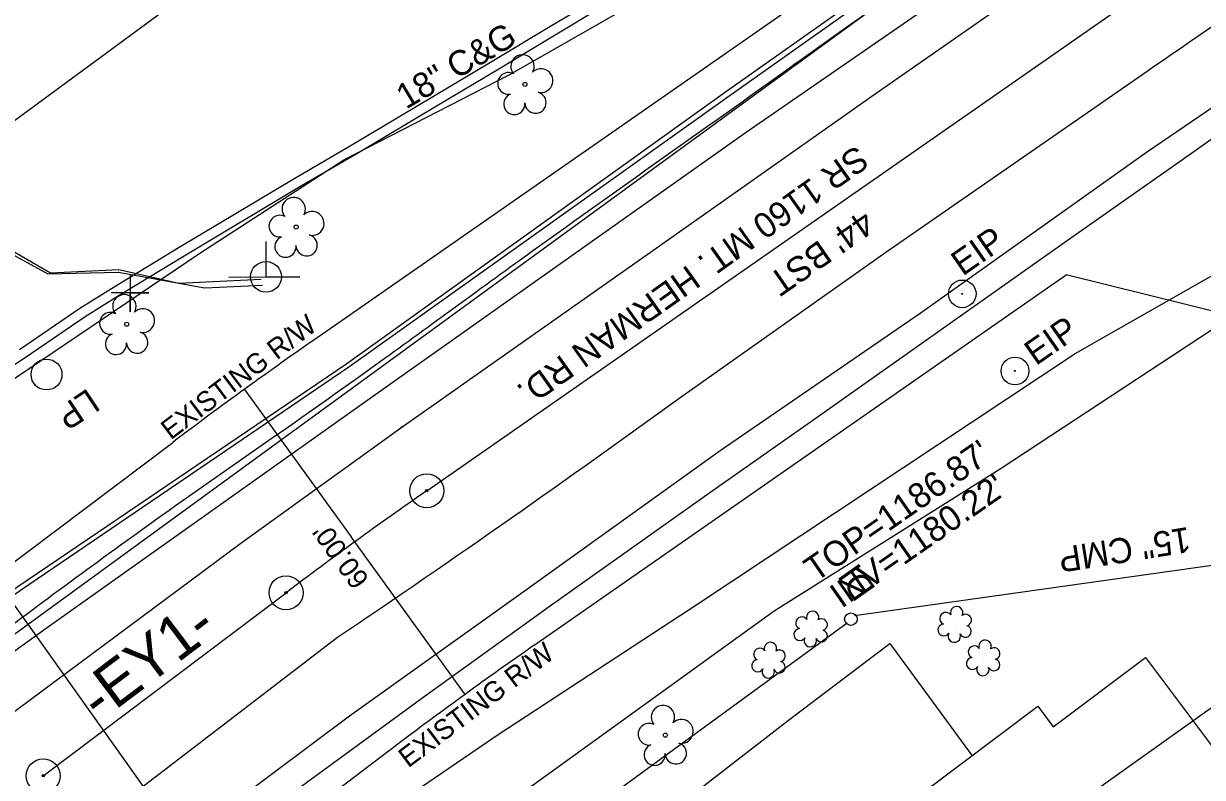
# Model space of a CAD drawing. Extents: x 1262092 to 1264624, y 774970 to 778314.
# Drawn here: x 1263058.9 to 1263246.8, y 776337.8 to 776457.9 of the extents above; entities that cross this region are included whole.
import ezdxf

# ---------------------------------------------------------------- set-up
doc = ezdxf.new("R2010")
doc.units = 0
for name, color, linetype in [('COGO Default Parcel', 7, 'Continuous'), ('Exist DTM Spot Elevation CELL', 7, 'Continuous'), ('Exist Horizontal Alignment', 7, 'Continuous'), ('Exist Horizontal Alignment Direction Label', 7, 'Continuous'), ('Exist Horizontal Alignment Tick Label', 7, 'Continuous'), ('Exist Horizontal Alignment Tick Large', 7, 'Continuous'), ('Exist Horizontal Alignment Tick Small', 7, 'Continuous'), ('Exist Property Iron Pin CELL', 7, 'Continuous'), ('Exist Property Iron Pin Text', 7, 'Continuous'), ('Exist Right of Way Line', 7, 'Continuous'), ('Exist Right of Way Line Text', 7, 'Continuous'), ('Exist Right of Way Width CELL', 7, 'Continuous'), ('Exist Roads Curbs', 7, 'Continuous'), ('Exist Roads EOP', 7, 'Continuous'), ('Exist Roads EOP Other', 7, 'Continuous'), ('Exist Roads EOT', 7, 'Continuous'), ('Exist Structure Minor Drop Inlet', 7, 'Continuous'), ('Exist Structure Minor Drop Inlet Text', 7, 'Continuous'), ('Exist Structure Minor Drop Inlet Top Elevation', 7, 'Continuous'), ('Exist Structure Minor Pipes CMP 15 Inch', 7, 'Continuous'), ('Exist Structure Minor Pipes CMP 15 Inch Invert', 7, 'Continuous'), ('Exist Structure Minor Pipes CMP 15 Inch Text', 7, 'Continuous'), ('Exist Utilities Gas UG Line SUE LOS B', 7, 'Continuous'), ('Exist Utilities Other Pole Text', 7, 'Continuous'), ('Exist Utilities Power Joint Use Telephone CELL', 7, 'Continuous'), ('Exist Utilities Power UG Cable SUE LOS B', 7, 'Continuous'), ('Exist Utilities Sanitary Sewer UG Line', 7, 'Continuous'), ('Exist Utilities Telephone UG Conduit SUE LOS B', 7, 'Continuous'), ('Exist Utilities Telephone UG FO SUE LOS B', 7, 'Continuous'), ('Exist Utilities TV UG FO Cable SUE LOS B', 7, 'Continuous'), ('Prop Horizontal Alignment', 7, 'Continuous'), ('Prop Shade Medium', 7, 'Continuous'), ('Prop Superelevation Label', 7, 'Continuous'), ('Sheet Sticker Incomplete CELL', 7, 'Continuous'), ('Typical Text Label CELL', 7, 'Continuous')]:
    doc.layers.add(name, color=color, linetype=linetype)

# ---------------------------------------------------------------- blocks, each defined once
blk = doc.blocks.new('EXIST DTM SPOT ELEVATION')
at = {"layer": 'Exist DTM Spot Elevation CELL'}
blk.add_lwpolyline([(0, 0.06), (0, -0.06), (0, 0), (0.06, 0), (-0.06, 0)], dxfattribs=at)
blk = doc.blocks.new('EXIST PROPERTY IRON PIN')
at = {"layer": 'Exist Property Iron Pin CELL'}
for radius in [0.0441, 0.00141]:
    blk.add_circle((0, 0), radius, dxfattribs=at)

msp = doc.modelspace()

# ---------------------------------------------------------------- linework, layer by layer
at = {"layer": 'COGO Default Parcel'}
for p, q in [((1263129.41, 776264.25), (1263013.38, 776427.15)), ((1263276.19, 776368.79), (1263129.41, 776264.25))]:
    msp.add_line(p, q, dxfattribs=at)
at = {"layer": 'Exist Horizontal Alignment'}
for p, q in [((1263123.18, 776383.49), (1263698.47, 776784.16)), ((1263062.04, 776338.06), (1263100.74, 776367.24))]:
    msp.add_line(p, q, dxfattribs=at)
msp.add_arc((1263531.93, 775795.39), 716.2, 124.8, 127.01667, dxfattribs=at)
at = {"layer": 'Exist Horizontal Alignment Tick Label'}
for centre, radius in [((1263123.18, 776383.49), 2.71), ((1263123.18, 776383.49), 0.187), ((1263100.74, 776367.24), 2.71), ((1263100.74, 776367.24), 0.187), ((1263062.04, 776338.06), 2.71), ((1263062.04, 776338.06), 0.187)]:
    msp.add_circle(centre, radius, dxfattribs=at)
at = {"layer": 'Exist Horizontal Alignment Tick Large'}
for p, q in [((1263184.45, 776361.28), (1263184.45, 776361.28)), ((1263207.4, 776362.01), (1263207.4, 776362.01)), ((1263177.73, 776356.31), (1263177.73, 776356.31)), ((1263211.94, 776356.67), (1263211.94, 776356.67))]:
    msp.add_line(p, q, dxfattribs=at)
for centre, radius, start, end in [((1263207.63, 776364.05), 0.99, 334.8391, 200.4717), ((1263182.97, 776362.41), 0.968, 35.8908, 245.4216), ((1263184.68, 776363.32), 0.99, 334.8391, 200.4717), ((1263205.92, 776363.13), 0.968, 35.8908, 245.4216), ((1263209.07, 776362.88), 0.929, 284.4567, 126.0861), ((1263182.65, 776360.57), 0.955, 95.1099, 327.9534), ((1263186.09, 776360.35), 0.937, 204.9913, 73.4601), ((1263186.12, 776362.15), 0.929, 284.4567, 126.0861), ((1263205.6, 776361.3), 0.955, 95.1099, 327.9534), ((1263209.04, 776361.08), 0.937, 204.9913, 73.4601), ((1263177.96, 776358.35), 0.99, 334.8391, 200.4717), ((1263184.32, 776359.6), 0.984, 151.2797, 21.387), ((1263207.27, 776360.32), 0.984, 151.2797, 21.387), ((1263212.17, 776358.71), 0.99, 334.8391, 200.4717), ((1263176.25, 776357.44), 0.968, 35.8908, 245.4216), ((1263179.4, 776357.18), 0.929, 284.4567, 126.0861), ((1263210.46, 776357.8), 0.968, 35.8908, 245.4216), ((1263213.61, 776357.54), 0.929, 284.4567, 126.0861), ((1263175.93, 776355.61), 0.955, 95.1099, 327.9534), ((1263179.37, 776355.38), 0.937, 204.9913, 73.4601), ((1263210.14, 776355.96), 0.955, 95.1099, 327.9534), ((1263213.58, 776355.74), 0.937, 204.9913, 73.4601), ((1263177.6, 776354.63), 0.984, 151.2797, 21.387), ((1263211.81, 776354.99), 0.984, 151.2797, 21.387)]:
    msp.add_arc(centre, radius, start, end, dxfattribs=at)
at = {"layer": 'Exist Horizontal Alignment Tick Small'}
for p, q in [((1263138.82, 776448.25), (1263138.82, 776448.25)), ((1263102.35, 776425.51), (1263102.35, 776425.51)), ((1263075.35, 776410.02), (1263075.35, 776410.02)), ((1263161.21, 776344.54), (1263161.21, 776344.54))]:
    msp.add_line(p, q, dxfattribs=at)
for centre in [(1263138.82, 776448.25), (1263102.35, 776425.51), (1263075.35, 776410.02), (1263161.21, 776344.54)]:
    msp.add_circle(centre, 0.326, dxfattribs=at)
for centre, radius, start, end in [((1263138.44, 776451.13), 1.86, 330.1651, 219.7134), ((1263136.22, 776448.41), 1.73, 62.6636, 279.3457), ((1263141.37, 776448.84), 1.9, 257.1011, 134.1999), ((1263137.12, 776445.13), 1.69, 111.5671, 6.231), ((1263140.5, 776445.35), 1.7, 181.2822, 74.56), ((1263101.97, 776428.38), 1.86, 330.1651, 219.7134), ((1263099.75, 776425.66), 1.73, 62.6636, 279.3457), ((1263104.9, 776426.09), 1.9, 257.1011, 134.1999), ((1263100.65, 776422.39), 1.69, 111.5671, 6.231), ((1263104.03, 776422.61), 1.7, 181.2822, 74.56), ((1263074.97, 776412.89), 1.86, 330.1651, 219.7134), ((1263077.9, 776410.6), 1.9, 257.1011, 134.1999), ((1263072.75, 776410.17), 1.73, 62.6636, 279.3457), ((1263073.65, 776406.89), 1.69, 111.5671, 6.231), ((1263077.02, 776407.12), 1.7, 181.2822, 74.56), ((1263160.82, 776347.41), 1.86, 330.1651, 219.7134), ((1263158.6, 776344.69), 1.73, 62.6636, 279.3457), ((1263163.76, 776345.13), 1.9, 257.1011, 134.1999), ((1263159.5, 776341.42), 1.69, 111.5671, 6.231), ((1263162.88, 776341.64), 1.7, 181.2822, 74.56)]:
    msp.add_arc(centre, radius, start, end, dxfattribs=at)
at = {"layer": 'Exist Right of Way Line'}
for p, q in [((1263106.05, 776408.12), (1263226.42, 776491.95)), ((1263350.65, 776386.89), (1263225.07, 776417.89)), ((1263043.98, 776362.02), (1263082.68, 776391.2)), ((1263080.1, 776314.11), (1263118.8, 776343.29))]:
    msp.add_line(p, q, dxfattribs=at)
msp.add_lwpolyline([(1263140.3, 776358.86), (1263140.32, 776358.87), (1263225.07, 776417.89)], dxfattribs=at)
for centre, radius, start, end in [((1263531.93, 775795.39), 746.2, 124.80113, 127.01667), ((1263585.26, 775720.24), 778.35, 124.86679, 125.86153), ((1263531.93, 775795.39), 686.2, 125.92832, 127.01667)]:
    msp.add_arc(centre, radius, start, end, dxfattribs=at)
at = {"layer": 'Exist Right of Way Width CELL'}
for p in [(1263094.11, 776399.65), (1263129.28, 776351.04)]:
    msp.add_line(p, (1263111.13, 776376.13), dxfattribs=at)
at = {"layer": 'Exist Roads Curbs'}
msp.add_lwpolyline([(1263216.03, 776506.6), (1263213.8, 776504.87), (1263209.23, 776501.42), (1263199.46, 776494.02), (1263185.09, 776483.09), (1263175.96, 776476.24), (1263172.02, 776473.25), (1263167.68, 776470.14), (1263159.5, 776465.39), (1263151.22, 776460.64), (1263143.62, 776456.08), (1263134.41, 776450.52), (1263125.08, 776444.97), (1263112.03, 776437.18), (1263102.92, 776431.9), (1263084.51, 776420.89), (1263074.17, 776414.6), (1263068.75, 776411.21), (1263059.14, 776404.65), (1263050.93, 776399.25)], dxfattribs=at)
at = {"layer": 'Exist Roads EOP'}
msp.add_lwpolyline([(1263305.84, 776482.42), (1263293.83, 776475.54), (1263265.44, 776456.13), (1263237.91, 776437.41), (1263201.8, 776411.74), (1263169.95, 776389.85), (1263138.16, 776367.04), (1263110.85, 776347.57), (1263079.86, 776324.43)], dxfattribs=at)
msp.add_spline([(1263270.33, 776616.29), (1263277.95, 776601.77), (1263283.55, 776577.66), (1263282.77, 776555.16), (1263273.97, 776526.11), (1263261.3, 776509.47), (1263242.63, 776493.72), (1263207.21, 776469.34), (1263177.26, 776448.17), (1263136.42, 776419.06), (1263111.74, 776401.16), (1263077.88, 776377.33), (1263049.63, 776356.49)], degree=3, dxfattribs=at)
at = {"layer": 'Exist Roads EOP Other'}
msp.add_lwpolyline([(1263175.16, 776477.62), (1263175, 776477.5), (1263171.08, 776474.52), (1263166.82, 776471.47), (1263158.71, 776466.76), (1263150.42, 776462), (1263142.8, 776457.43), (1263133.6, 776451.88), (1263124.27, 776446.33), (1263111.23, 776438.54), (1263102.12, 776433.26), (1263083.7, 776422.25), (1263073.34, 776415.94), (1263067.89, 776412.54), (1263058.26, 776405.96)], dxfattribs=at)
at = {"layer": 'Exist Roads EOT'}
msp.add_line((1263068.23, 776328.99), (1263108.97, 776360.14), dxfattribs=at)
for points in [[(1263055.86, 776347.14), (1263093.56, 776375.13), (1263119.4, 776393.79), (1263119.03, 776393.52), (1263161.16, 776423.14), (1263194.13, 776446.35), (1263238.24, 776477.15), (1263266.32, 776496.83), (1263297.06, 776517.2), (1263326.49, 776538.85)], [(1263163.71, 776398.45), (1263196.36, 776421.53), (1263237.98, 776450.36)]]:
    msp.add_lwpolyline(points, dxfattribs=at)
msp.add_ellipse((1261990.55, 778026.7), major_axis=(1423.31, 1437.35), ratio=0.9919, start_param=4.514715, end_param=4.547755, dxfattribs=at)
msp.add_spline([(1263237.98, 776450.36), (1263259.66, 776465.25), (1263288.73, 776485.12), (1263318.56, 776505.53), (1263341.21, 776520.98)], degree=3, dxfattribs=at)
at = {"layer": 'Exist Structure Minor Drop Inlet'}
msp.add_circle((1263190.78, 776363.02), 1, dxfattribs=at)
at = {"layer": 'Exist Structure Minor Pipes CMP 15 Inch'}
for p, q in [((1263252.08, 776372.11), (1263191.34, 776363.55)), ((1263190.16, 776362.41), (1263109.03, 776303.24))]:
    msp.add_line(p, q, dxfattribs=at)
at = {"layer": 'Exist Utilities Gas UG Line SUE LOS B'}
msp.add_lwpolyline([(1263088.04, 776312.91), (1263134.74, 776344.77), (1263166.36, 776365.45), (1263226.51, 776405.34), (1263250.34, 776418.92), (1263298.57, 776447.74), (1263334.08, 776473.24), (1263349.9, 776479.97), (1263361.13, 776478.82), (1263375.51, 776470.89), (1263383.73, 776466.14), (1263405.71, 776440.43), (1263407.22, 776439.34), (1263410.02, 776440.45), (1263416.58, 776444.66), (1263442.39, 776461.54), (1263455.06, 776469.2), (1263497.14, 776495.83), (1263506.92, 776503.01), (1263523.32, 776512.13)], dxfattribs=at)
msp.add_circle((1263062.57, 776402.01), 2.46, dxfattribs=at)
at = {"layer": 'Exist Utilities Power Joint Use Telephone CELL'}
msp.add_line((1263097.55, 776417.57), (1263097.55, 776417.57), dxfattribs=at)
msp.add_lwpolyline([(1263091.61, 776417.57), (1263102.95, 776417.54), (1263097.55, 776417.55), (1263097.55, 776423.2)], dxfattribs=at)
msp.add_circle((1263097.55, 776417.58), 2.45, dxfattribs=at)
at = {"layer": 'Exist Utilities Power UG Cable SUE LOS B'}
for points in [[(1263022.78, 776438.19), (1263051.86, 776397.67), (1263087, 776421.34), (1263109.96, 776436.23), (1263136.29, 776449.79), (1263136.3, 776449.76), (1263171.16, 776469.68), (1263198.08, 776488.52), (1263216, 776499.92), (1263233.17, 776512.29), (1263248.6, 776528.82), (1263250.89, 776550.61)], [(1263097.53, 776305.86), (1263178.57, 776364.37), (1263214.74, 776387.07), (1263250.28, 776410.44), (1263260.49, 776418.39), (1263273.79, 776434.51), (1263276.64, 776442.13), (1263274.73, 776450.65)]]:
    msp.add_lwpolyline(points, dxfattribs=at)
at = {"layer": 'Exist Utilities Sanitary Sewer UG Line'}
msp.add_line((1263242.49, 776495.42), (1263052.88, 776357.28), dxfattribs=at)
at = {"layer": 'Exist Utilities Telephone UG Conduit SUE LOS B'}
msp.add_lwpolyline([(1263043.64, 776434.4), (1263054.59, 776422.52), (1263062.8, 776418.07), (1263074.05, 776418.34), (1263073.99, 776418.33), (1263087.81, 776415.84), (1263096.99, 776416.25)], dxfattribs=at)
at = {"layer": 'Exist Utilities Telephone UG FO SUE LOS B'}
for points in [[(1263021.33, 776341.46), (1263058.42, 776367.65), (1263110.75, 776403.22), (1263171.15, 776446.27), (1263216.08, 776478.09), (1263246.91, 776502.79), (1263255.49, 776511.46), (1263262.4, 776520.59), (1263269.32, 776532.47), (1263272.46, 776540.67), (1263275.57, 776549.73), (1263276.9, 776560.75), (1263278.67, 776572.93), (1263277.86, 776582.26), (1263271.87, 776600.58)], [(1263024.86, 776334.48), (1263062.52, 776361.6), (1263114.14, 776398.23), (1263173.93, 776440.52), (1263220.36, 776472.64), (1263237.1, 776485.66), (1263257.13, 776505.55), (1263265.04, 776516.51), (1263272.71, 776529.97), (1263279.51, 776549.09), (1263281.5, 776560.23), (1263281.1, 776573), (1263279.91, 776583.04), (1263274.08, 776601.58)], [(1263021.72, 776341.54), (1263057.98, 776368.23), (1263110.45, 776403.76), (1263170.81, 776447.07), (1263215.57, 776478.73), (1263246.59, 776504.02), (1263255.25, 776512.33), (1263261.65, 776521.31), (1263268.82, 776532.91), (1263271.24, 776541.94), (1263272.91, 776550.27), (1263275.25, 776562.72), (1263276.67, 776572.87), (1263276.15, 776581.92), (1263270.16, 776599.83)]]:
    msp.add_lwpolyline(points, dxfattribs=at)
at = {"layer": 'Exist Utilities TV UG FO Cable SUE LOS B'}
msp.add_lwpolyline([(1263044.07, 776434.76), (1263055.52, 776422.67), (1263063.22, 776418.24), (1263074.07, 776418.75), (1263083.66, 776416.56), (1263096.76, 776417.23)], dxfattribs=at)
at = {"layer": 'Prop Shade Medium'}
for points in [[(1263081.14, 776459.88), (1263036.72, 776427.24), (1262997.83, 776480.18), (1262999.26, 776481.23), (1262996.83, 776484.5), (1262991.13, 776480.27), (1262983.97, 776489.92), (1262991.31, 776495.37), (1262966.61, 776528.65), (1263006.2, 776558.04), (1263044.1, 776507), (1263045.49, 776508.05)], [(1263127.76, 776279.33), (1263220.58, 776349.14), (1263223.03, 776345.88), (1263237.72, 776356.93), (1263248.43, 776342.69), (1263261.5, 776352.52), (1263286.02, 776348.9), (1263282.63, 776324.42), (1263269.46, 776314.52), (1263280.36, 776300.03), (1263265.61, 776288.93), (1263268.01, 776285.74), (1263175.28, 776216), (1263172.83, 776219.26), (1263158.17, 776208.23), (1263115.45, 776265.04), (1263130.18, 776276.11)]]:
    msp.add_lwpolyline(points, close=True, dxfattribs=at)
at = {"layer": 'Prop Superelevation Label'}
msp.add_lwpolyline([(1263117.82, 776299.09), (1263125.68, 776304.98), (1263141.69, 776317), (1263165.27, 776334.87), (1263180.86, 776346.91), (1263196.97, 776359.15), (1263210.11, 776341.27)], dxfattribs=at)
at = {"layer": 'Typical Text Label CELL'}
msp.add_lwpolyline([(1263265.37, 776451.7), (1263245.06, 776437.24), (1263224.57, 776422.83), (1263204.28, 776408.5), (1263183.82, 776394.04), (1263168.28, 776383.15), (1263143.08, 776365.26), (1263122.74, 776350.63), (1263102.61, 776335.93), (1263077.64, 776317.18), (1263052.62, 776298.39), (1263042.89, 776290.68), (1263037.94, 776286.47), (1263033.33, 776282.2), (1263024.91, 776273.72), (1263023.27, 776271.88)], dxfattribs=at)

# ---------------------------------------------------------------- block references
at = {"layer": 'Exist DTM Spot Elevation CELL', "xscale": 50, "yscale": 50}
msp.add_blockref('EXIST DTM SPOT ELEVATION', (1263075.88, 776415.03), dxfattribs=at)
at = {"layer": 'Exist Property Iron Pin CELL', "xscale": 50, "yscale": 50}
for p in [(1263208.53, 776414.87), (1263216.93, 776402.58)]:
    msp.add_blockref('EXIST PROPERTY IRON PIN', p, dxfattribs=at)

# ---------------------------------------------------------------- texts
at = {"layer": 'Exist Horizontal Alignment Direction Label'}
msp.add_text('-EY1-', height=7, rotation=37.0167, dxfattribs=at).set_placement((1263071.02, 776346.6))
at = {"layer": 'Exist Property Iron Pin Text'}
for p in [(1263208.59, 776417.61), (1263220.27, 776403.33)]:
    msp.add_text('EIP', height=4, rotation=34.8555, dxfattribs=at).set_placement(p)
at = {"layer": 'Exist Right of Way Line Text'}
for p in [(1263082.36, 776391.5), (1263120.22, 776339.23)]:
    msp.add_text('EXISTING R/W', height=3.2, rotation=37.0167, dxfattribs=at).set_placement(p)
at = {"layer": 'Exist Right of Way Width CELL'}
msp.add_text("60.00'", height=3.2, rotation=125.8876, dxfattribs=at).set_placement((1263114.13, 776369.37))
at = {"layer": 'Exist Structure Minor Drop Inlet Text'}
msp.add_text('DI', height=4, rotation=125.2645, dxfattribs=at).set_placement((1263194.86, 776367.86))
at = {"layer": 'Exist Structure Minor Drop Inlet Top Elevation'}
msp.add_text("TOP=1186.87'", height=4, rotation=34.8555, dxfattribs=at).set_placement((1263185.16, 776368.84))
at = {"layer": 'Exist Structure Minor Pipes CMP 15 Inch Invert'}
msp.add_text("INV=1180.22'", height=4, rotation=34.8555, dxfattribs=at).set_placement((1263189.29, 776364.66))
at = {"layer": 'Exist Structure Minor Pipes CMP 15 Inch Text'}
msp.add_text('15" CMP', height=4, rotation=189.146, dxfattribs=at).set_placement((1263244.57, 776377.74))
at = {"layer": 'Exist Utilities Other Pole Text'}
msp.add_text('LP', height=4, rotation=213.6695, dxfattribs=at).set_placement((1263069.19, 776399.92))
at = {"layer": 'Prop Horizontal Alignment'}
for s, rotation, p in [('SR 1160 MT. HERMAN RD.', 215.3869, (1263191.71, 776438.7)), ("44' BST", 214.8555, (1263192.75, 776428.43))]:
    msp.add_text(s, height=4, rotation=rotation, dxfattribs=at).set_placement(p)
at = {"layer": 'Sheet Sticker Incomplete CELL'}
msp.add_text('18" C&G', height=4, rotation=30.7645, dxfattribs=at).set_placement((1263119.87, 776444.2))

doc.saveas('drawing.dxf')
